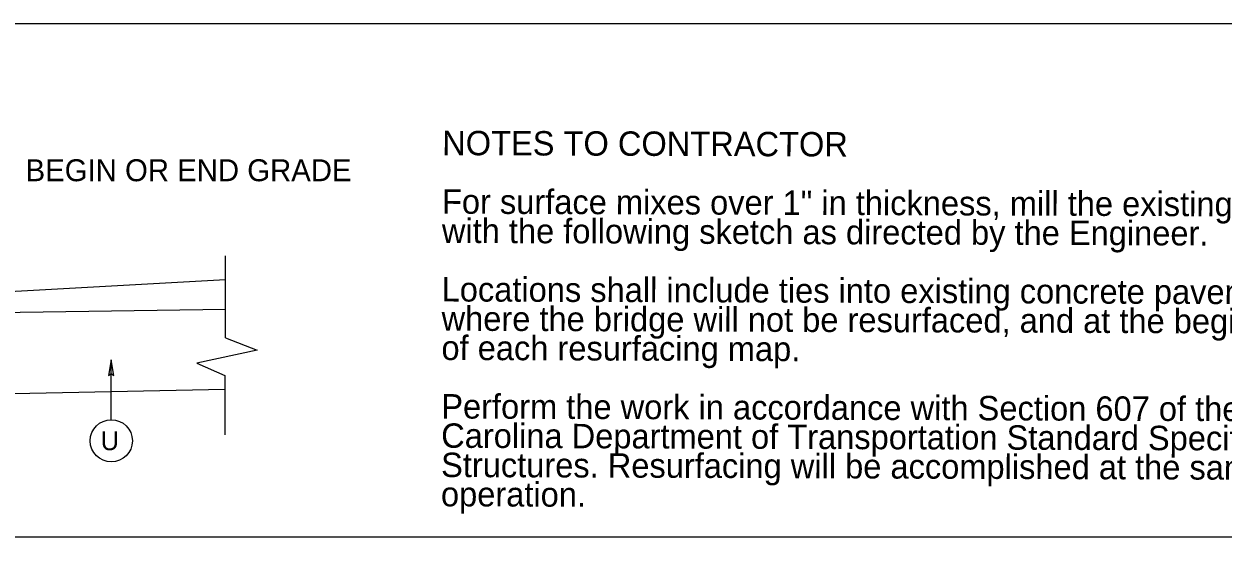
# Model space of a CAD drawing. Extents: x 573748 to 574632, y -54663 to -53209.
# Drawn here: x 574154.1 to 574236.2, y -53296 to -53260.9 of the extents above; entities that cross this region are included whole.
import ezdxf

# ---------------------------------------------------------------- set-up
doc = ezdxf.new("R2010")
doc.units = 0
for name, color, linetype in [('Old_Level_1', 7, 'Continuous'), ('Prop Dimension', 7, 'Continuous'), ('Prop Pavement Schedule Description CELL', 7, 'Continuous'), ('Typical ID Circle CELL', 7, 'Continuous'), ('Typical Terminator CELL', 7, 'Continuous'), ('Typical Text ID Circle CELL', 7, 'Continuous')]:
    doc.layers.add(name, color=color, linetype=linetype)

msp = doc.modelspace()

# ---------------------------------------------------------------- linework, layer by layer
at = {"layer": 'Prop Dimension'}
for p, q in [((574167.878, -53282.357), (574167.878, -53276.743)), ((574116.927, -53281.193), (574167.878, -53278.366)), ((574167.878, -53280.416), (574100.532, -53281.443)), ((574167.878, -53282.357), (574170.061, -53283.196)), ((574170.061, -53283.196), (574165.921, -53284.097)), ((574165.921, -53284.097), (574167.845, -53284.941)), ((574167.845, -53284.941), (574167.845, -53288.991)), ((574167.845, -53285.903), (574100.532, -53287.249))]:
    msp.add_line(p, q, dxfattribs=at)
at = {"layer": 'Prop Pavement Schedule Description CELL'}
msp.add_lwpolyline([(574084.041, -53295.977), (574271.128, -53295.977), (574271.128, -53260.902), (574084.041, -53260.902)], close=True, dxfattribs=at)
at = {"layer": 'Typical ID Circle CELL'}
msp.add_line((574160.073, -53287.958), (574160.073, -53283.875), dxfattribs=at)
msp.add_circle((574160.073, -53289.401), 1.443, dxfattribs=at)
at = {"layer": 'Typical Terminator CELL'}
msp.add_lwpolyline([(574160.254, -53284.929), (574160.073, -53283.875), (574159.885, -53284.935), (574160.073, -53284.8)], close=True, dxfattribs=at)

# ---------------------------------------------------------------- texts
at = {"layer": 'Old_Level_1'}
for s, height, p in [('NOTES TO CONTRACTOR', 1.66725, (574182.699, -53269.87)), ('For surface mixes over 1" in thickness, mill the existing pavement in accordance', 1.66725, (574182.686, -53273.871)), ('with the following sketch as directed by the Engineer.', 1.66725, (574182.679, -53275.872)), ('Locations shall include ties into existing concrete pavement, at bridge approaches ', 1.66725, (574182.665, -53279.873)), ('where the bridge will not be resurfaced, and at the beginning and ending point', 1.66725, (574182.659, -53281.874)), ('of each resurfacing map.', 1.66725, (574182.652, -53283.874)), ('Perform the work in accordance with Section 607 of the January 2024 North', 1.66725, (574182.638, -53287.875)), ('Carolina Department of Transportation Standard Specifications for Roads and', 1.66725, (574182.632, -53289.876)), ('Structures. Resurfacing will be accomplished at the same time as the milling ', 1.66725, (574182.625, -53291.877)), ('operation.', 1.6672, (574182.618, -53293.877))]:
    msp.add_text(s, height=height, rotation=359.80703, dxfattribs=at).set_placement(p)
at = {"layer": 'Prop Dimension'}
msp.add_text('BEGIN OR END GRADE', height=1.5, rotation=360, dxfattribs=at).set_placement((574154.213, -53271.652))
at = {"layer": 'Typical Text ID Circle CELL'}
msp.add_text('U', height=1.291, dxfattribs=at).set_placement((574159.352, -53290.044))

doc.saveas('drawing.dxf')
